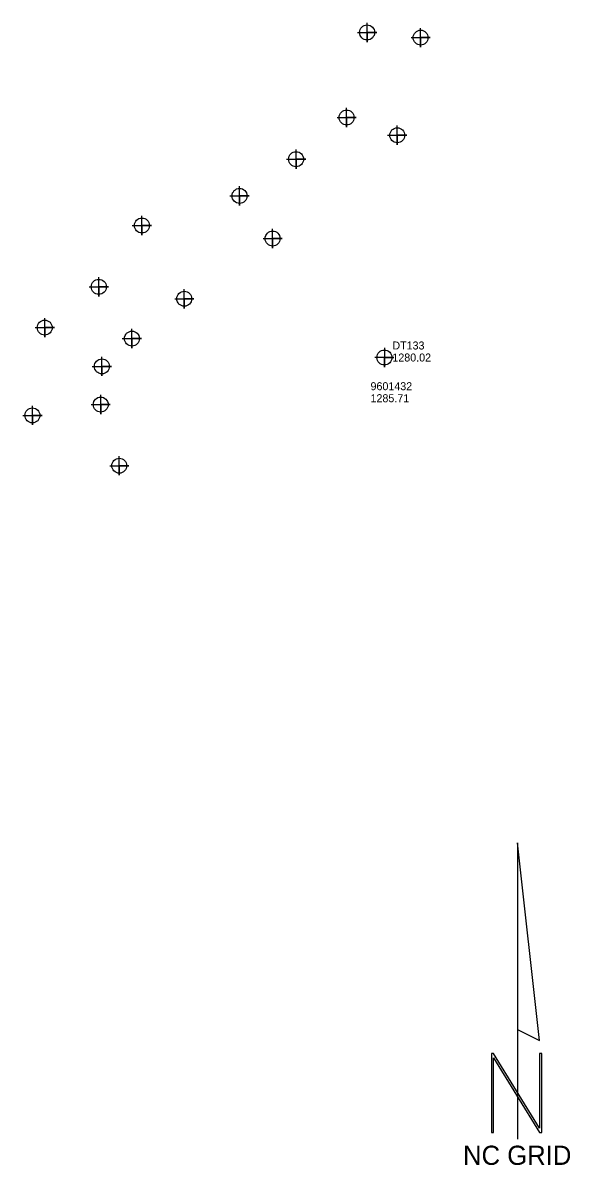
# Model space of a CAD drawing. Extents: x 1382088 to 1383563, y 883989 to 884716.
# Drawn here: x 1382595.2 to 1382766.3, y 884359.3 to 884716.1 of the extents above; entities that cross this region are included whole.
import ezdxf

# ---------------------------------------------------------------- set-up
doc = ezdxf.new("R2010")
doc.units = 0
for name, color, linetype in [('COGO Default Point Elevation', 7, 'Continuous'), ('COGO Default Point Number', 7, 'Continuous'), ('CTL North Arrow NAD 83 NA 2011 CELL', 7, 'Continuous'), ('Exist Hydro Stream or Body of Water Cogo Point CELL', 7, 'Continuous'), ('Exist Structure Minor Pipes CMP 15 Inch Cogo Elevation', 7, 'Continuous'), ('Exist Structure Minor Pipes CMP 15 Inch Cogo Number', 7, 'Continuous'), ('Exist Structure Minor Pipes CMP 15 Inch Cogo Point CELL', 7, 'Continuous')]:
    doc.layers.add(name, color=color, linetype=linetype)

msp = doc.modelspace()

# ---------------------------------------------------------------- linework, layer by layer
at = {"layer": 'CTL North Arrow NAD 83 NA 2011 CELL'}
msp.add_line((1382750.08, 884372.7), (1382750.08, 884372.7), dxfattribs=at)
for points in [[(1382749.93, 884459.99), (1382749.93, 884401.67), (1382756.81, 884398.23)], [(1382741.71, 884369.44), (1382742.39, 884369.44), (1382742.39, 884392.77), (1382756.81, 884369.44), (1382757.49, 884369.44), (1382757.49, 884394.13), (1382756.81, 884394.13), (1382756.81, 884370.8), (1382742.39, 884394.13), (1382741.71, 884394.13)]]:
    msp.add_lwpolyline(points, close=True, dxfattribs=at)
msp.add_lwpolyline([(1382749.93, 884401.67), (1382749.93, 884367.37)], dxfattribs=at)
at = {"layer": 'Exist Hydro Stream or Body of Water Cogo Point CELL'}
for points in [[(1382699.87, 884713.06), (1382705.87, 884713.06), (1382702.87, 884713.06), (1382702.87, 884710.06), (1382702.87, 884716.06)], [(1382716.61, 884711.44), (1382722.61, 884711.44), (1382719.61, 884711.44), (1382719.61, 884708.44), (1382719.61, 884714.44)], [(1382693.47, 884686.5), (1382699.47, 884686.5), (1382696.47, 884686.5), (1382696.47, 884683.5), (1382696.47, 884689.5)], [(1382709.29, 884680.95), (1382715.29, 884680.95), (1382712.29, 884680.95), (1382712.29, 884677.95), (1382712.29, 884683.95)], [(1382677.67, 884673.48), (1382683.67, 884673.48), (1382680.67, 884673.48), (1382680.67, 884670.48), (1382680.67, 884676.48)], [(1382660, 884662.02), (1382666, 884662.02), (1382663, 884662.02), (1382663, 884659.02), (1382663, 884665.02)], [(1382629.47, 884652.77), (1382635.47, 884652.77), (1382632.47, 884652.77), (1382632.47, 884649.77), (1382632.47, 884655.77)], [(1382670.34, 884648.7), (1382676.34, 884648.7), (1382673.34, 884648.7), (1382673.34, 884645.7), (1382673.34, 884651.7)], [(1382616, 884633.61), (1382622, 884633.61), (1382619, 884633.61), (1382619, 884630.61), (1382619, 884636.61)], [(1382642.72, 884629.89), (1382648.72, 884629.89), (1382645.72, 884629.89), (1382645.72, 884626.89), (1382645.72, 884632.89)], [(1382599.1, 884620.87), (1382605.1, 884620.87), (1382602.1, 884620.87), (1382602.1, 884617.87), (1382602.1, 884623.87)], [(1382626.35, 884617.45), (1382632.35, 884617.45), (1382629.35, 884617.45), (1382629.35, 884614.45), (1382629.35, 884620.45)], [(1382616.96, 884608.77), (1382622.96, 884608.77), (1382619.96, 884608.77), (1382619.96, 884605.77), (1382619.96, 884611.77)], [(1382616.59, 884596.84), (1382622.59, 884596.84), (1382619.59, 884596.84), (1382619.59, 884593.84), (1382619.59, 884599.84)], [(1382595.25, 884593.46), (1382601.25, 884593.46), (1382598.25, 884593.46), (1382598.25, 884590.46), (1382598.25, 884596.46)], [(1382622.4, 884577.75), (1382628.4, 884577.75), (1382625.4, 884577.75), (1382625.4, 884574.75), (1382625.4, 884580.75)]]:
    msp.add_lwpolyline(points, dxfattribs=at)
for centre in [(1382702.87, 884713.06), (1382719.61, 884711.44), (1382696.47, 884686.5), (1382712.29, 884680.95), (1382680.67, 884673.48), (1382663, 884662.02), (1382632.47, 884652.77), (1382673.34, 884648.7), (1382619, 884633.61), (1382645.72, 884629.89), (1382602.1, 884620.87), (1382629.35, 884617.45), (1382619.96, 884608.77), (1382619.59, 884596.84), (1382598.25, 884593.46), (1382625.4, 884577.75)]:
    msp.add_circle(centre, 2.34, dxfattribs=at)
at = {"layer": 'Exist Structure Minor Pipes CMP 15 Inch Cogo Point CELL'}
msp.add_lwpolyline([(1382708.27, 884614.54), (1382708.27, 884608.54), (1382708.27, 884611.54), (1382711.27, 884611.54), (1382705.27, 884611.54)], dxfattribs=at)
msp.add_circle((1382708.27, 884611.54), 2.34, dxfattribs=at)

# ---------------------------------------------------------------- texts
at = {"layer": 'COGO Default Point Elevation'}
msp.add_text('1285.71', height=2.5, dxfattribs=at).set_placement((1382703.94, 884597.57))
at = {"layer": 'COGO Default Point Number'}
msp.add_text('9601432', height=2.5, dxfattribs=at).set_placement((1382703.94, 884601.32))
at = {"layer": 'CTL North Arrow NAD 83 NA 2011 CELL'}
msp.add_text('NC GRID', height=6, dxfattribs=at).set_placement((1382732.85, 884359.37))
at = {"layer": 'Exist Structure Minor Pipes CMP 15 Inch Cogo Elevation'}
msp.add_text('1280.02', height=2.5, dxfattribs=at).set_placement((1382710.77, 884610.29))
at = {"layer": 'Exist Structure Minor Pipes CMP 15 Inch Cogo Number'}
msp.add_text('DT133', height=2.5, dxfattribs=at).set_placement((1382710.77, 884614.04))

doc.saveas('drawing.dxf')
